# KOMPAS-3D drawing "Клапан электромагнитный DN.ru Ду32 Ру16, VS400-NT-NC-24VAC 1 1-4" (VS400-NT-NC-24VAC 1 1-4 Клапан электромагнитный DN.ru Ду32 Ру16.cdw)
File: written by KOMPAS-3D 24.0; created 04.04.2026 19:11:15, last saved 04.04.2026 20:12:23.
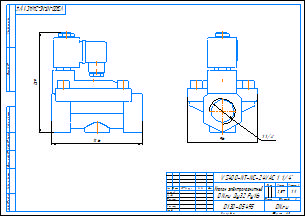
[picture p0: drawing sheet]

Document properties: c3d_UniqueCompID: ef56311e-7521-43dc-8291-0e6108b3d81d; Обозначение: VS400-ET-NC-220VAC 1; Наименование: Клапан электромагнитный DN.ru Ду25 Ру16; Автор: artio; Класс точности: c; Знак неуказанной шероховатости: Шероховатость не задана; Рассекать на разрезах: Да; c3d_UniqueCompID: ef56311e-7521-43dc-8291-0e6108b3d81d; Обозначение: VS400-ET-NC-220VAC 1-2; Наименование: Клапан электромагнитный DN.ru Ду15 Ру16; Автор: artio; Класс точности: c; Знак неуказанной шероховатости: Шероховатость не задана; Рассекать на разрезах: Да; c3d_UniqueCompID: ef56311e-7521-43dc-8291-0e6108b3d81d; Обозначение: VS400-ET-NC-220VAC 3-4; Наименование: Клапан электромагнитный DN.ru Ду20 Ру16; Автор: artio; Класс точности: c; Знак неуказанной шероховатости: Шероховатость не задана; Рассекать на разрезах: Да; c3d_UniqueCompID: ef56311e-7521-43dc-8291-0e6108b3d81d; Обозначение: VS400-ET-NC-220VAC 1 1-4; Наименование: Клапан электромагнитный DN.ru Ду32 Ру16; Автор: artio; Класс точности: c; Знак неуказанной шероховатости: Шероховатость не задана; Рассекать на разрезах: Да; c3d_UniqueCompID: ef56311e-7521-43dc-8291-0e6108b3d81d; Обозначение: VS400-ET-NC-220VAC 3-8; Наименование: Клапан электромагнитный DN.ru Ду10 Ру16; Автор: artio; Класс точности: c; Знак неуказанной шероховатости: Шероховатость не задана; Рассекать на разрезах: Да; Автор: artio; Форматы листов документа: A3; Полное имя файла: VS400-NT-NC-24VAC 1 1-4 Клапан электромагнитный DN.ru Ду32 Ру16.m3d; Масса: 2.569; Наименование: Клапан электромагнитный DN.ru Ду32 Ру16; Количество листов документа: 1; Примечание: D130-05495

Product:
- Body: Тело 1  | qty 1
    Масса: 4.144257
- Part/product: Клапан электромагнитный DN.ru Ду32 Ру16  | designation VS400-NT-NC-24VAC 1 1-4
    Масса: 2.569
    Раздел спецификации: Прочие изделия
    Примечание: D130-05495
    additional columns: ef56311e-7521-43dc-8291-0e6108b3d81d; VS400-ET-NC-220VAC 1 1-4; artio; c; Шероховатость не задана; Да

Views: Вид 1, Спереди
Referenced files in C:\Users\artio\OneDrive\Рабочий стол\Клапан электромагнитный DN.ru\VS400-ET-NC\VS400-ET-NC-24VDC\: VS400-ET-NC-24VDC 3-8 Клапан электромагнитный DN.ru Ду10 Ру16.m3d
Referenced files in C:\Users\artio\OneDrive\Рабочий стол\Клапан электромагнитный DN.ru\VS400-NT-NC\VS400-NT-NC-24VAC\: VS400-NT-NC-24VAC 1 1-4 Клапан электромагнитный DN.ru Ду32 Ру16.m3d
Referenced files in C:\Users\artio\OneDrive\Рабочий стол\Клапан электромагнитный DN.ru\VS400-ET-NC\: VS400-ET-NC-24VDC 3-8 Клапан электромагнитный DN.ru Ду10 Ру16.cdw
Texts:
  VS400-NT-NC-24VAC 1 1-4
  Клапан электромагнитный
  DN.ru Ду32 Ру16
  VS400-NT-NC-24VAC 1 1/4"
  VS400-NT-NC-24VAC 1 1/4"-
  Клапан электромагнитный DN.ru Ду32 Ру16
  VS400-NT-NC-24VAC 1 1-4 Клапан электромагнитный DN.ru Ду32 Ру16
Dimensions and other numbers on the sheet: 0; 3; 2; 4; 96; 1 1/4"; 1:1; 1; 2,57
